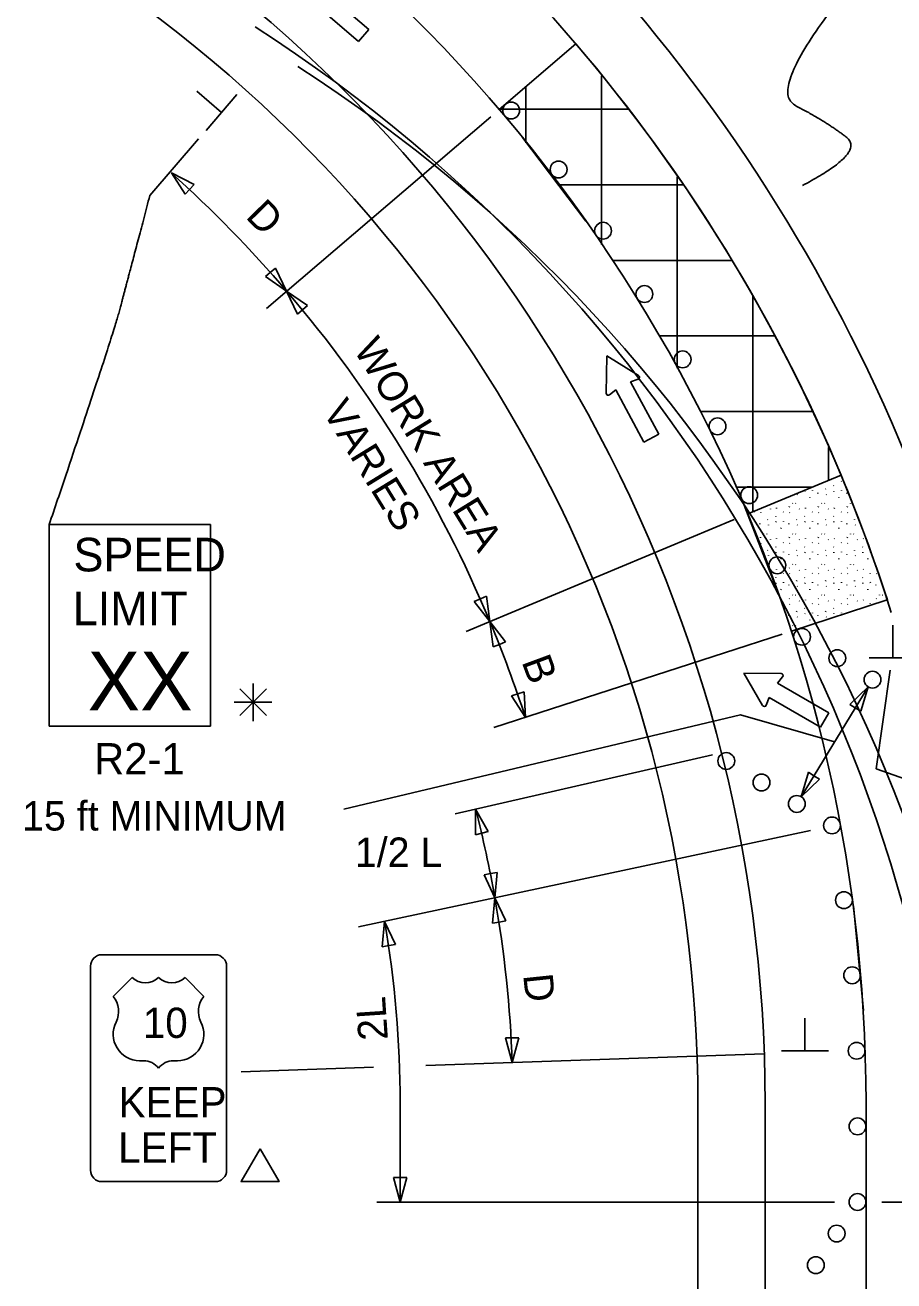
# Model space of a CAD drawing. Extents: x 16335 to 18464, y 5417 to 6974.
# Drawn here: x 16725.1 to 16931.8, y 6522.4 to 6821.2 of the extents above; entities that cross this region are included whole.
import ezdxf

# ---------------------------------------------------------------- set-up
doc = ezdxf.new("R2010")
doc.units = 0
for name, color, linetype in [('ALI_LEGAL_EX', 7, 'Continuous'), ('MT_SCRATCH_LEVEL_A', 7, 'Continuous'), ('MT_SCRATCH_LEVEL_E', 7, 'Continuous'), ('PAVT_EDGE_EX', 7, 'Continuous'), ('TRAFFIC_SIGNS_PR', 7, 'Continuous'), ('TYPICAL_EX', 7, 'Continuous'), ('TYPICAL_TEXT_DIMEN_PR', 7, 'Continuous')]:
    doc.layers.add(name, color=color, linetype=linetype)

msp = doc.modelspace()

# ---------------------------------------------------------------- linework, layer by layer
at = {"layer": 'ALI_LEGAL_EX'}
msp.add_line((16925.13, 6287.02), (16925.13, 6564.7), dxfattribs=at)
for points in [[(16858.51, 6774.55), (16843.42, 6794.48)], [(16904.63, 6685.11), (16895.58, 6708.42)], [(16924.57, 6586.71), (16922.17, 6611.6)]]:
    msp.add_lwpolyline(points, dxfattribs=at)
for centre, end in [((16561.13, 6564.7), 53.7921), ((16583.12, 6514.52), 57.2958), ((16593.27, 6505.1), 57.2958)]:
    msp.add_arc(centre, 364, 0, end, dxfattribs=at)
at = {"layer": 'MT_SCRATCH_LEVEL_A'}
for p, q in [((16856.12, 6816.75), (16837.87, 6801.16)), ((16862.22, 6769.02), (16862.22, 6809.19)), ((16844.22, 6793.23), (16844.22, 6806.58)), ((16837.98, 6801.25), (16868.51, 6801.25)), ((16880.22, 6739.56), (16880.22, 6785.14)), ((16852.22, 6783.25), (16881.53, 6783.25)), ((16864.87, 6765.25), (16893.08, 6765.25)), ((16898.22, 6705.39), (16898.22, 6756.82)), ((16875.96, 6747.25), (16903.31, 6747.25)), ((16885.68, 6729.25), (16912.35, 6729.25)), ((16916.22, 6712.9), (16916.22, 6720.72)), ((16897.05, 6704.9), (16919.2, 6714.14)), ((16919.2, 6714.14), (16897.05, 6704.9)), ((16919.21, 6712.69), (16919.26, 6712.61)), ((16894.17, 6711.25), (16912.27, 6711.25)), ((16908.79, 6709.56), (16908.85, 6709.48)), ((16910.57, 6710.23), (16910.62, 6710.34)), ((16912.37, 6710.48), (16912.42, 6710.4)), ((16913.65, 6709.9), (16913.66, 6709.78)), ((16915.49, 6710.76), (16915.54, 6710.87)), ((16915.68, 6709.56), (16915.73, 6709.48)), ((16917.42, 6711.63), (16917.47, 6711.55)), ((16917.46, 6710.23), (16917.51, 6710.34)), ((16919.26, 6710.48), (16919.31, 6710.4)), ((16920.54, 6709.9), (16920.55, 6709.78)), ((16906.88, 6706.53), (16906.94, 6706.64)), ((16907.65, 6707.49), (16907.7, 6707.41)), ((16908.39, 6707.46), (16908.44, 6707.38)), ((16911.75, 6708.72), (16911.8, 6708.84)), ((16913.77, 6706.53), (16913.82, 6706.64)), ((16914.53, 6707.49), (16914.59, 6707.41)), ((16915.27, 6707.46), (16915.32, 6707.38)), ((16918.64, 6708.72), (16918.69, 6708.84)), ((16920.66, 6706.53), (16920.71, 6706.64)), ((16921.42, 6707.49), (16921.47, 6707.41)), ((16898.55, 6705.4), (16898.6, 6705.32)), ((16900.08, 6705.26), (16900.13, 6705.18)), ((16901.72, 6703.47), (16901.77, 6703.59)), ((16902.37, 6706.08), (16902.42, 6706)), ((16903.64, 6704.34), (16903.69, 6704.26)), ((16903.81, 6706.23), (16903.87, 6706.35)), ((16905.43, 6705.4), (16905.49, 6705.32)), ((16906.96, 6705.26), (16907.01, 6705.18)), ((16908.6, 6703.47), (16908.66, 6703.59)), ((16909.25, 6706.08), (16909.31, 6706)), ((16910.53, 6704.34), (16910.58, 6704.26)), ((16910.7, 6706.23), (16910.75, 6706.35)), ((16912.32, 6705.4), (16912.37, 6705.32)), ((16913.85, 6705.26), (16913.9, 6705.18)), ((16915.49, 6703.47), (16915.54, 6703.59)), ((16916.14, 6706.08), (16916.19, 6706)), ((16917.42, 6704.34), (16917.47, 6704.26)), ((16917.59, 6706.23), (16917.64, 6706.35)), ((16919.21, 6705.4), (16919.26, 6705.32)), ((16920.74, 6705.26), (16920.79, 6705.18)), ((16922.38, 6703.47), (16922.43, 6703.59)), ((16898.6, 6703.19), (16898.65, 6703.11)), ((16899.88, 6702.62), (16899.89, 6702.5)), ((16901.91, 6702.27), (16901.96, 6702.19)), ((16903.69, 6702.94), (16903.74, 6703.06)), ((16904.86, 6701.44), (16904.92, 6701.56)), ((16905.48, 6703.19), (16905.53, 6703.11)), ((16906.76, 6702.62), (16906.78, 6702.5)), ((16908.79, 6702.27), (16908.85, 6702.19)), ((16910.57, 6702.94), (16910.62, 6703.06)), ((16911.75, 6701.44), (16911.8, 6701.56)), ((16912.37, 6703.19), (16912.42, 6703.11)), ((16913.65, 6702.62), (16913.66, 6702.5)), ((16915.68, 6702.27), (16915.73, 6702.19)), ((16917.46, 6702.94), (16917.51, 6703.06)), ((16918.64, 6701.44), (16918.69, 6701.56)), ((16919.26, 6703.19), (16919.31, 6703.11)), ((16920.54, 6702.62), (16920.55, 6702.5)), ((16922.57, 6702.27), (16922.62, 6702.19)), ((16900, 6699.24), (16900.05, 6699.36)), ((16900.08, 6697.98), (16900.13, 6697.9)), ((16900.76, 6700.2), (16900.81, 6700.12)), ((16901.5, 6700.17), (16901.55, 6700.1)), ((16902.37, 6698.79), (16902.42, 6698.72)), ((16903.81, 6698.94), (16903.87, 6699.06)), ((16905.43, 6698.12), (16905.49, 6698.04)), ((16906.88, 6699.24), (16906.94, 6699.36)), ((16906.96, 6697.98), (16907.01, 6697.9)), ((16907.65, 6700.2), (16907.7, 6700.12)), ((16908.39, 6700.17), (16908.44, 6700.1)), ((16909.25, 6698.79), (16909.31, 6698.72)), ((16910.7, 6698.94), (16910.75, 6699.06)), ((16912.32, 6698.12), (16912.37, 6698.04)), ((16913.77, 6699.24), (16913.82, 6699.36)), ((16913.85, 6697.98), (16913.9, 6697.9)), ((16914.53, 6700.2), (16914.59, 6700.12)), ((16915.27, 6700.17), (16915.32, 6700.1)), ((16916.14, 6698.79), (16916.19, 6698.72)), ((16917.59, 6698.94), (16917.64, 6699.06)), ((16919.21, 6698.12), (16919.26, 6698.04)), ((16920.66, 6699.24), (16920.71, 6699.36)), ((16920.74, 6697.98), (16920.79, 6697.9)), ((16921.42, 6700.2), (16921.47, 6700.12)), ((16922.16, 6700.17), (16922.21, 6700.1)), ((16923.03, 6698.79), (16923.08, 6698.72)), ((16924.48, 6698.94), (16924.53, 6699.06)), ((16901.72, 6696.19), (16901.77, 6696.3)), ((16901.91, 6694.99), (16901.96, 6694.91)), ((16903.64, 6697.06), (16903.69, 6696.98)), ((16903.69, 6695.66), (16903.74, 6695.77)), ((16905.48, 6695.91), (16905.53, 6695.83)), ((16906.76, 6695.33), (16906.78, 6695.21)), ((16908.6, 6696.19), (16908.66, 6696.3)), ((16908.79, 6694.99), (16908.85, 6694.91)), ((16910.53, 6697.06), (16910.58, 6696.98)), ((16910.57, 6695.66), (16910.62, 6695.77)), ((16912.37, 6695.91), (16912.42, 6695.83)), ((16913.65, 6695.33), (16913.66, 6695.21)), ((16915.49, 6696.19), (16915.54, 6696.3)), ((16915.68, 6694.99), (16915.73, 6694.91)), ((16917.42, 6697.06), (16917.47, 6696.98)), ((16917.46, 6695.66), (16917.51, 6695.77)), ((16919.26, 6695.91), (16919.31, 6695.83)), ((16920.54, 6695.33), (16920.55, 6695.21)), ((16922.38, 6696.19), (16922.43, 6696.3)), ((16922.57, 6694.99), (16922.62, 6694.91)), ((16924.31, 6697.06), (16924.36, 6696.98)), ((16924.35, 6695.66), (16924.4, 6695.77)), ((16926.15, 6695.91), (16926.2, 6695.83)), ((16902.37, 6691.51), (16902.42, 6691.43)), ((16903.81, 6691.66), (16903.87, 6691.78)), ((16904.86, 6694.15), (16904.92, 6694.27)), ((16906.88, 6691.96), (16906.94, 6692.07)), ((16907.65, 6692.92), (16907.7, 6692.84)), ((16908.39, 6692.89), (16908.44, 6692.81)), ((16909.25, 6691.51), (16909.31, 6691.43)), ((16910.7, 6691.66), (16910.75, 6691.78)), ((16911.75, 6694.15), (16911.8, 6694.27)), ((16913.77, 6691.96), (16913.82, 6692.07)), ((16914.53, 6692.92), (16914.59, 6692.84)), ((16915.27, 6692.89), (16915.32, 6692.81)), ((16916.14, 6691.51), (16916.19, 6691.43)), ((16917.59, 6691.66), (16917.64, 6691.78)), ((16918.64, 6694.15), (16918.69, 6694.27)), ((16920.66, 6691.96), (16920.71, 6692.07)), ((16921.42, 6692.92), (16921.47, 6692.84)), ((16922.16, 6692.89), (16922.21, 6692.81)), ((16923.03, 6691.51), (16923.08, 6691.43)), ((16924.48, 6691.66), (16924.53, 6691.78)), ((16925.53, 6694.15), (16925.58, 6694.27)), ((16927.55, 6691.96), (16927.58, 6692.03)), ((16903.64, 6689.77), (16903.69, 6689.69)), ((16905.43, 6690.83), (16905.49, 6690.75)), ((16905.48, 6688.62), (16905.53, 6688.54)), ((16906.96, 6690.69), (16907.01, 6690.61)), ((16908.6, 6688.9), (16908.66, 6689.02)), ((16910.53, 6689.77), (16910.58, 6689.69)), ((16912.32, 6690.83), (16912.37, 6690.75)), ((16912.37, 6688.62), (16912.42, 6688.54)), ((16913.85, 6690.69), (16913.9, 6690.61)), ((16915.49, 6688.9), (16915.54, 6689.02)), ((16917.42, 6689.77), (16917.47, 6689.69)), ((16919.21, 6690.83), (16919.26, 6690.75)), ((16919.26, 6688.62), (16919.31, 6688.54)), ((16920.74, 6690.69), (16920.79, 6690.61)), ((16922.38, 6688.9), (16922.43, 6689.02)), ((16924.31, 6689.77), (16924.36, 6689.69)), ((16926.1, 6690.83), (16926.15, 6690.75)), ((16926.15, 6688.62), (16926.2, 6688.54)), ((16927.63, 6690.69), (16927.68, 6690.61)), ((16903.69, 6688.37), (16903.74, 6688.49)), ((16904.86, 6686.87), (16904.92, 6686.99)), ((16906.76, 6688.05), (16906.78, 6687.93)), ((16907.65, 6685.63), (16907.7, 6685.56)), ((16908.39, 6685.6), (16908.44, 6685.53)), ((16908.79, 6687.7), (16908.85, 6687.62)), ((16910.57, 6688.37), (16910.62, 6688.49)), ((16911.75, 6686.87), (16911.8, 6686.99)), ((16913.65, 6688.05), (16913.66, 6687.93)), ((16914.53, 6685.63), (16914.59, 6685.56)), ((16915.27, 6685.6), (16915.32, 6685.53)), ((16915.68, 6687.7), (16915.73, 6687.62)), ((16917.46, 6688.37), (16917.51, 6688.49)), ((16918.64, 6686.87), (16918.69, 6686.99)), ((16920.54, 6688.05), (16920.55, 6687.93)), ((16921.42, 6685.63), (16921.47, 6685.56)), ((16922.16, 6685.6), (16922.21, 6685.53)), ((16922.57, 6687.7), (16922.62, 6687.62)), ((16924.35, 6688.37), (16924.4, 6688.49)), ((16925.53, 6686.87), (16925.58, 6686.99)), ((16927.43, 6688.05), (16927.44, 6687.93)), ((16928.31, 6685.63), (16928.36, 6685.56)), ((16929.05, 6685.6), (16929.1, 6685.53)), ((16905.43, 6683.55), (16905.49, 6683.47)), ((16906.88, 6684.67), (16906.94, 6684.79)), ((16906.96, 6683.41), (16907.01, 6683.33)), ((16907.37, 6677.02), (16930.2, 6684.43)), ((16909.25, 6684.22), (16909.31, 6684.15)), ((16910.7, 6684.38), (16910.75, 6684.49)), ((16912.32, 6683.55), (16912.37, 6683.47)), ((16913.77, 6684.67), (16913.82, 6684.79)), ((16913.85, 6683.41), (16913.9, 6683.33)), ((16916.14, 6684.22), (16916.19, 6684.15)), ((16917.59, 6684.38), (16917.64, 6684.49)), ((16919.21, 6683.55), (16919.26, 6683.47)), ((16920.66, 6684.67), (16920.71, 6684.79)), ((16920.74, 6683.41), (16920.79, 6683.33)), ((16923.03, 6684.22), (16923.08, 6684.15)), ((16924.48, 6684.38), (16924.53, 6684.49)), ((16926.1, 6683.55), (16926.15, 6683.47)), ((16927.55, 6684.67), (16927.6, 6684.79)), ((16906.76, 6680.76), (16906.78, 6680.65)), ((16908.6, 6681.62), (16908.66, 6681.73)), ((16908.79, 6680.42), (16908.85, 6680.34)), ((16910.53, 6682.49), (16910.58, 6682.41)), ((16910.57, 6681.09), (16910.62, 6681.2)), ((16911.75, 6679.58), (16911.8, 6679.7)), ((16912.37, 6681.34), (16912.42, 6681.26)), ((16913.65, 6680.76), (16913.66, 6680.65)), ((16915.49, 6681.62), (16915.54, 6681.73)), ((16915.68, 6680.42), (16915.73, 6680.34)), ((16917.42, 6682.49), (16917.47, 6682.41)), ((16917.46, 6681.09), (16917.51, 6681.2)), ((16919.26, 6681.34), (16919.31, 6681.26)), ((16907.65, 6678.35), (16907.7, 6678.27)), ((16908.39, 6678.32), (16908.44, 6678.24))]:
    msp.add_line(p, q, dxfattribs=at)
for start, end in [(22.6538, 40.5126), (17.974, 22.6538)]:
    msp.add_arc((16561.14, 6564.7), 388, start, end, dxfattribs=at)
at = {"layer": 'MT_SCRATCH_LEVEL_E'}
for p, q in [((16806.83, 6820.15), (16796.78, 6828.8)), ((16794.34, 6825.96), (16804.39, 6817.32)), ((16804.39, 6817.32), (16806.83, 6820.15))]:
    msp.add_line(p, q, dxfattribs=at)
at = {"layer": 'PAVT_EDGE_EX'}
for p, q in [((16885.13, 6564.7), (16885.13, 6156.73)), ((16901.13, 6564.7), (16901.13, 6156.73))]:
    msp.add_line(p, q, dxfattribs=at)
for radius, start, end in [(404, 21.0961, 61.7914), (388, 17.512, 61.7914), (340, 0, 59.4823), (324, 0, 59.3448)]:
    msp.add_arc((16561.13, 6564.7), radius, start, end, dxfattribs=at)
at = {"layer": 'TRAFFIC_SIGNS_PR'}
for p, q in [((16730.81, 6702.36), (16769.21, 6702.36)), ((16730.81, 6654.36), (16730.81, 6702.36)), ((16769.21, 6654.36), (16769.21, 6702.36)), ((16730.81, 6654.36), (16769.21, 6654.36)), ((16770.33, 6599.99), (16743.33, 6599.99)), ((16740.63, 6597.29), (16740.63, 6548.69)), ((16773.03, 6548.69), (16773.03, 6597.29)), ((16743.33, 6545.99), (16770.33, 6545.99))]:
    msp.add_line(p, q, dxfattribs=at)
for centre in [(16840.72, 6800.9), (16852, 6786.87), (16862.57, 6772.3), (16872.41, 6757.23), (16881.51, 6741.68), (16889.81, 6725.74), (16897.33, 6709.38), (16904.04, 6692.68), (16909.91, 6675.67), (16918.3, 6670.56), (16926.68, 6665.45), (16891.89, 6646.1), (16900.27, 6640.99), (16908.66, 6635.88), (16917.04, 6630.77), (16917.04, 6630.77), (16919.88, 6612.99), (16921.84, 6595.1), (16922.9, 6577.14), (16923.12, 6559.14), (16923.12, 6541.14), (16923.12, 6541.14), (16918.15, 6533.63), (16913.18, 6526.12)]:
    msp.add_circle(centre, 2, dxfattribs=at)
for centre, start, end in [((16743.33, 6597.29), 90, 180), ((16770.33, 6597.29), 0, 90), ((16743.33, 6548.69), 180, 270), ((16770.33, 6548.69), 270, 0)]:
    msp.add_arc(centre, 2.7, start, end, dxfattribs=at)
at = {"layer": 'TYPICAL_EX'}
for p, q in [((16746.03, 6590.09), (16750.53, 6594.59)), ((16767.63, 6590.09), (16763.13, 6594.59)), ((16752.32, 6574.78), (16753.22, 6574.78)), ((16761.33, 6574.78), (16760.44, 6574.78))]:
    msp.add_line(p, q, dxfattribs=at)
for centre, radius, start, end in [((16753.68, 6597.86), 4.55, 226.1404, 313.8596), ((16759.98, 6597.86), 4.55, 226.1404, 313.8596), ((16741.76, 6586.48), 5.58, 333.0977, 40.1936), ((16771.89, 6586.48), 5.58, 139.8064, 206.9023), ((16752.33, 6581.07), 6.29, 152.6698, 269.9013), ((16761.32, 6581.07), 6.29, 270.0987, 27.3302), ((16753.23, 6570.27), 4.51, 37.1038, 90.1385), ((16760.42, 6570.27), 4.51, 89.8615, 142.8962)]:
    msp.add_arc(centre, radius, start, end, dxfattribs=at)
at = {"layer": 'TYPICAL_TEXT_DIMEN_PR'}
for p, q in [((16837.87, 6801.16), (16856.11, 6816.75)), ((16771.83, 6800.44), (16765.92, 6805.52)), ((16775.49, 6804.71), (16768.16, 6796.18)), ((16782.47, 6753.82), (16835.84, 6799.43)), ((16754.75, 6780.66), (16766.36, 6794.16)), ((16763.18, 6780.97), (16759.87, 6786.05)), ((16759.87, 6786.05), (16765.28, 6783.3)), ((16764.23, 6782.13), (16763.18, 6780.97)), ((16765.28, 6783.3), (16764.23, 6782.13)), ((16783.49, 6762.4), (16784.68, 6763.42)), ((16784.68, 6763.42), (16787.29, 6757.94)), ((16782.29, 6761.38), (16783.49, 6762.4)), ((16787.29, 6757.94), (16782.29, 6761.38)), ((16789.91, 6752.47), (16787.29, 6757.94)), ((16787.29, 6757.94), (16792.3, 6754.51)), ((16792.3, 6754.51), (16791.1, 6753.49)), ((16791.1, 6753.49), (16789.91, 6752.47)), ((16863.48, 6742.52), (16863.29, 6733.64)), ((16871.04, 6737.82), (16863.48, 6742.52)), ((16869.11, 6736.33), (16870.94, 6736.94)), ((16875.82, 6723.89), (16869.11, 6736.33)), ((16864.09, 6733.24), (16865.6, 6734.44)), ((16865.6, 6734.44), (16872.31, 6721.99)), ((16872.31, 6721.99), (16875.82, 6723.89)), ((16897.05, 6704.9), (16919.2, 6714.14)), ((16830.01, 6676.91), (16893.8, 6703.54)), ((16831.95, 6684.08), (16833.4, 6684.68)), ((16835.66, 6679.27), (16831.95, 6684.08)), ((16833.4, 6684.68), (16834.85, 6685.29)), ((16834.85, 6685.29), (16835.66, 6679.27)), ((16836.47, 6673.26), (16835.66, 6679.27)), ((16835.66, 6679.27), (16839.37, 6674.47)), ((16931.49, 6670.66), (16931.49, 6678.45)), ((16837.92, 6673.86), (16836.47, 6673.26)), ((16836.63, 6654.07), (16905.16, 6676.31)), ((16839.37, 6674.47), (16837.92, 6673.86)), ((16937.12, 6670.66), (16925.87, 6670.66)), ((16930.86, 6667.69), (16927.57, 6644.26)), ((16904.93, 6666.94), (16896.03, 6666.98)), ((16896.03, 6666.98), (16900.52, 6659.32)), ((16904.06, 6664.66), (16905.3, 6666.13)), ((16916.3, 6657.58), (16904.06, 6664.66)), ((16926.68, 6665.45), (16926.68, 6665.45)), ((16776.14, 6663.3), (16782.51, 6656.92)), ((16782.51, 6663.3), (16776.14, 6656.92)), ((16779.32, 6660.11), (16779.32, 6664.57)), ((16840.79, 6661.58), (16842.28, 6662.07)), ((16842.28, 6662.07), (16843.78, 6662.55)), ((16843.78, 6662.55), (16844.09, 6656.49)), ((16909.7, 6637.59), (16925.64, 6663.74)), ((16921.25, 6659.55), (16925.64, 6663.74)), ((16925.64, 6663.74), (16923.93, 6657.92)), ((16779.32, 6660.11), (16774.79, 6660.11)), ((16779.32, 6660.11), (16782.51, 6660.11)), ((16779.32, 6660.11), (16783.8, 6660.11)), ((16779.32, 6660.11), (16779.32, 6655.61)), ((16844.09, 6656.49), (16840.79, 6661.58)), ((16901.4, 6659.4), (16902.06, 6661.21)), ((16902.06, 6661.21), (16914.3, 6654.12)), ((16922.59, 6658.74), (16921.25, 6659.55)), ((16923.93, 6657.92), (16922.59, 6658.74)), ((16895.24, 6657.1), (16800.9, 6634.63)), ((16917.67, 6650.66), (16895.24, 6657.1)), ((16914.3, 6654.12), (16916.3, 6657.58)), ((16888.59, 6647.57), (16827.38, 6633.51)), ((16927.57, 6644.26), (17009.73, 6614.66)), ((16909.7, 6637.59), (16911.41, 6643.41)), ((16914.09, 6641.77), (16909.7, 6637.59)), ((16911.41, 6643.41), (16912.75, 6642.59)), ((16912.75, 6642.59), (16914.09, 6641.77)), ((16832.2, 6628.56), (16832.26, 6634.63)), ((16832.26, 6634.63), (16835.24, 6629.34)), ((16804.43, 6606.62), (16911.9, 6629.56)), ((16833.72, 6628.95), (16832.2, 6628.56)), ((16835.24, 6629.34), (16833.72, 6628.95)), ((16834.27, 6619.04), (16835.82, 6619.31)), ((16836.84, 6613.54), (16834.27, 6619.04)), ((16835.82, 6619.31), (16837.36, 6619.59)), ((16837.36, 6619.59), (16836.84, 6613.54)), ((16836.31, 6607.49), (16836.84, 6613.54)), ((16836.84, 6613.54), (16839.41, 6608.04)), ((16810.06, 6601.89), (16810.59, 6607.94)), ((16810.59, 6607.94), (16813.16, 6602.44)), ((16839.41, 6608.04), (16837.86, 6607.77)), ((16837.86, 6607.77), (16836.31, 6607.49)), ((16811.61, 6602.16), (16810.06, 6601.89)), ((16813.16, 6602.44), (16811.61, 6602.16)), ((16910.61, 6577.09), (16910.61, 6584.88)), ((16840.97, 6574.34), (16839.4, 6580.2)), ((16839.4, 6580.2), (16840.97, 6580.2)), ((16840.97, 6580.2), (16842.54, 6580.2)), ((16842.54, 6580.2), (16840.97, 6574.34)), ((16820.43, 6573.63), (16900.93, 6576.4)), ((16916.24, 6577.09), (16904.99, 6577.09)), ((16776.49, 6572.12), (16807.93, 6573.2)), ((16814.31, 6564.7), (16814.31, 6541.14)), ((16814.31, 6541.14), (16812.74, 6547)), ((16812.74, 6547), (16814.31, 6547)), ((16814.31, 6547), (16815.88, 6547)), ((16815.88, 6547), (16814.31, 6541.14)), ((16917.63, 6541.14), (16808.77, 6541.14)), ((16928.89, 6541.14), (17032.15, 6541.14))]:
    msp.add_line(p, q, dxfattribs=at)
msp.add_lwpolyline([(16780.99, 6553.82), (16776.46, 6545.99), (16785.51, 6545.99)], close=True, dxfattribs=at)
for centre, radius, start, end in [((16561.13, 6564.7), 297.48, 40.5126, 48.082), ((16561.13, 6564.7), 297.48, 22.6539, 40.5126), ((16870.77, 6737.4), 0.494, 288.3781, 58.115), ((16863.79, 6733.64), 0.494, 178.7668, 308.3057), ((16561.13, 6564.7), 297.48, 17.974, 22.6539), ((16904.92, 6666.44), 0.494, 319.9691, 89.7061), ((16900.94, 6659.57), 0.494, 210.3578, 339.8967), ((16561.13, 6564.7), 280, 10.0461, 14.4629), ((16561.13, 6564.7), 280, 1.9734, 10.046), ((16561.13, 6564.7), 253.18, 0, 9.834)]:
    msp.add_arc(centre, radius, start, end, dxfattribs=at)
for points in [[(16909.99, 6783.05), (16925.05, 6790.93), (16915.89, 6798.15), (16900.83, 6806.02), (16924.4, 6834.24)], [(16754.75, 6780.66), (16749.28, 6759.85), (16745.65, 6746.28), (16730.81, 6702.36)]]:
    msp.add_open_spline(points, degree=2, dxfattribs=at)

# ---------------------------------------------------------------- texts
at = {"layer": 'TRAFFIC_SIGNS_PR'}
for s, height, p in [('SPEED', 8, (16736.58, 6691.22)), ('LIMIT', 8, (16736.42, 6678.42)), ('XX', 14.031, (16739.93, 6658.12)), ('R2-1', 7.44, (16741.49, 6642.92)), ('10', 7.2, (16753.07, 6580.19)), ('KEEP', 7.2, (16747.31, 6561.29)), ('LEFT', 7.2, (16747.21, 6550.49))]:
    msp.add_text(s, height=height, dxfattribs=at).set_placement(p)
at = {"layer": 'TYPICAL_TEXT_DIMEN_PR'}
for s, rotation, p in [('D', 314.2974, (16777.3, 6775.52)), ('WORK AREA', 301.5829, (16803.06, 6744.07)), ('VARIES', 301.5829, (16795.66, 6729.37)), ('B', 290.315, (16843.13, 6669.76)), ('D', 276.0098, (16843.56, 6595.17)), ('2L', 93.8016, (16811.4, 6579.83))]:
    msp.add_text(s, height=7, rotation=rotation, dxfattribs=at).set_placement(p)
for s, p in [('15 ft MINIMUM', (16724.37, 6629.55)), ('1/2 L', (16803.53, 6620.89))]:
    msp.add_text(s, height=7, dxfattribs=at).set_placement(p)

doc.saveas('drawing.dxf')
